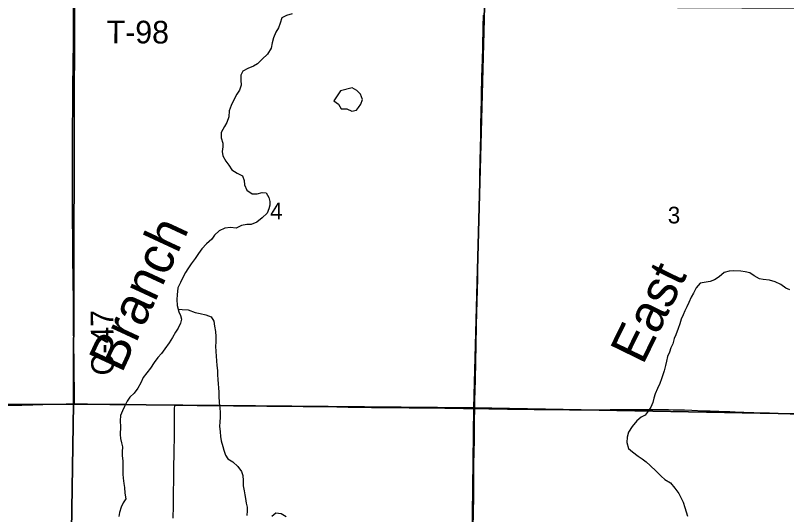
# Model space of a CAD drawing. Extents: x 0 to 34, y 0 to 22.
# Drawn here: x 3.385 to 4.352, y 16.769 to 17.395 of the extents above; entities that cross this region are included whole.
import ezdxf

# ---------------------------------------------------------------- set-up
doc = ezdxf.new("R2010")
doc.units = 0
for name, color, linetype in [('GM_X_County_Road', 7, 'Continuous'), ('GM_X_County_Road_Text', 7, 'Continuous'), ('GM_X_Minor_Lake', 7, 'Continuous'), ('GM_X_Minor_River', 7, 'Continuous'), ('GM_X_Minor_River_Text', 7, 'Continuous'), ('GM_X_Section', 7, 'Continuous'), ('GM_X_Section_Text', 7, 'Continuous'), ('GM_X_Township_Road', 7, 'Continuous'), ('GM_X_Township_Road_Text', 7, 'Continuous')]:
    doc.layers.add(name, color=color, linetype=linetype)

msp = doc.modelspace()

# ---------------------------------------------------------------- linework, layer by layer
at = {"layer": 'GM_X_County_Road'}
for points in [[(3.45945, 16.90815), (3.45949, 16.91151), (3.45951, 16.91491), (3.45933, 16.92889), (3.45926, 16.94257), (3.45913, 16.9522), (3.45894, 16.96494), (3.45873, 16.97769), (3.45843, 17.00846), (3.45828, 17.02711), (3.45821, 17.03643), (3.45806, 17.04483), (3.45798, 17.05509), (3.45793, 17.06285), (3.45785, 17.06782), (3.45775, 17.07248), (3.45755, 17.08304), (3.45746, 17.09236), (3.45733, 17.10572), (3.45725, 17.11412), (3.45711, 17.14023), (3.457, 17.15049), (3.45693, 17.16417), (3.45696, 17.18282), (3.45695, 17.20241), (3.45702, 17.21546), (3.457, 17.22852), (3.45711, 17.24096), (3.45718, 17.25277), (3.4572, 17.28199), (3.45746, 17.31121), (3.45766, 17.32893), (3.45804, 17.36748), (3.45838, 17.40478)], [(3.37291, 16.90601), (3.39342, 16.90665), (3.4074, 16.90706), (3.43287, 16.90789), (3.44904, 16.90816), (3.45931, 16.90815), (3.45945, 16.90815)], [(3.45945, 16.90815), (3.47577, 16.90794), (3.50218, 16.9076), (3.51554, 16.9075), (3.52394, 16.90749), (3.52798, 16.90742), (3.5373, 16.90715), (3.55345, 16.90698), (3.56184, 16.90685), (3.57178, 16.90673), (3.58503, 16.90663)], [(3.58312, 16.76464), (3.58337, 16.77956), (3.5836, 16.78919), (3.58376, 16.79757), (3.58387, 16.81186), (3.58411, 16.83051), (3.58433, 16.84419), (3.58454, 16.85506), (3.58464, 16.86097), (3.5848, 16.86903), (3.58475, 16.8771), (3.58475, 16.88021), (3.58484, 16.88767), (3.58498, 16.90135), (3.58503, 16.90663)], [(3.58503, 16.90663), (3.58763, 16.90662), (3.61312, 16.90613), (3.62088, 16.90602), (3.63579, 16.90592), (3.642, 16.90588), (3.64946, 16.90584), (3.65878, 16.90576), (3.66375, 16.9057), (3.67027, 16.90567), (3.67959, 16.9056), (3.70042, 16.90534), (3.72186, 16.90508), (3.73087, 16.905), (3.7461, 16.90483), (3.76226, 16.90462), (3.78805, 16.90439), (3.80235, 16.90414), (3.82069, 16.90385), (3.83188, 16.90366), (3.83808, 16.90357), (3.84944, 16.90354), (3.86309, 16.90335), (3.87893, 16.9032), (3.88888, 16.90318), (3.89976, 16.90311), (3.92338, 16.90277), (3.947, 16.90243), (3.95601, 16.90234), (3.96116, 16.9023)], [(3.96116, 16.9023), (3.97062, 16.90221), (3.9787, 16.90202), (3.99019, 16.90172), (4.0023, 16.90157), (4.01722, 16.90135), (4.02343, 16.90126), (4.02716, 16.90124), (4.03555, 16.90116), (4.04332, 16.90108), (4.05109, 16.90099), (4.05606, 16.90096), (4.06321, 16.90086), (4.0719, 16.90084), (4.07999, 16.90078), (4.08744, 16.90071), (4.09832, 16.90066), (4.10888, 16.90057), (4.11788, 16.90069), (4.13063, 16.90084), (4.14959, 16.90081), (4.15798, 16.90088), (4.16823, 16.90106), (4.1732, 16.90112), (4.1788, 16.90115), (4.18374, 16.9011), (4.18591, 16.90107), (4.18773, 16.90103), (4.18856, 16.901), (4.19227, 16.90099), (4.19755, 16.90095), (4.19783, 16.90093), (4.20279, 16.90088), (4.20401, 16.90087), (4.20961, 16.90078), (4.21737, 16.90061), (4.2239, 16.90038), (4.23321, 16.89997), (4.24781, 16.89952), (4.25589, 16.89924), (4.26675, 16.89882), (4.28072, 16.89834), (4.28724, 16.89806), (4.29842, 16.89777), (4.31084, 16.89733), (4.33041, 16.89662), (4.34781, 16.89599), (4.37296, 16.89492)]]:
    msp.add_lwpolyline(points, dxfattribs=at)
at = {"layer": 'GM_X_Minor_Lake'}
for points in [[(3.81528, 17.2799), (3.81818, 17.28383), (3.82025, 17.2899), (3.8178, 17.29634), (3.81345, 17.30127), (3.80739, 17.30449), (3.79302, 17.30088), (3.78451, 17.28799)], [(3.78451, 17.28799), (3.79038, 17.28382), (3.79359, 17.27832), (3.80078, 17.27795), (3.80702, 17.2753), (3.81288, 17.27662), (3.81528, 17.2799)]]:
    msp.add_lwpolyline(points, dxfattribs=at)
at = {"layer": 'GM_X_Minor_River'}
for points in [[(3.73212, 17.39736), (3.72531, 17.39527), (3.71926, 17.39224), (3.71737, 17.38579), (3.7151, 17.37991), (3.7117, 17.37422), (3.70886, 17.36721), (3.70735, 17.36095), (3.70584, 17.35413), (3.70149, 17.34673), (3.69487, 17.34028), (3.68901, 17.33459), (3.68371, 17.33156), (3.6769, 17.32852), (3.67029, 17.3253), (3.66802, 17.32018), (3.66802, 17.31392), (3.66839, 17.30786), (3.66631, 17.3016), (3.66291, 17.29648), (3.65932, 17.28927), (3.65591, 17.28226), (3.65345, 17.27581), (3.6527, 17.26804), (3.65024, 17.26083), (3.64759, 17.2559), (3.64343, 17.24832), (3.64324, 17.24168), (3.64532, 17.23524), (3.64532, 17.2305), (3.64438, 17.22443), (3.64532, 17.21932), (3.64911, 17.2123), (3.6527, 17.20756), (3.65686, 17.2015), (3.66348, 17.19733), (3.66991, 17.19411), (3.67218, 17.18805), (3.67237, 17.18293), (3.67539, 17.17591), (3.6822, 17.17156), (3.68844, 17.17156), (3.69449, 17.17327), (3.69979, 17.1727), (3.70319, 17.16682), (3.70433, 17.16209), (3.70414, 17.15735), (3.70319, 17.15261), (3.70111, 17.14711), (3.69468, 17.14161), (3.68788, 17.13611), (3.68088, 17.13326), (3.67539, 17.13326), (3.66877, 17.13193), (3.66215, 17.12852), (3.65478, 17.12928), (3.64797, 17.12851), (3.64059, 17.12529), (3.63492, 17.1196), (3.63171, 17.11486), (3.62509, 17.1086), (3.61922, 17.10272), (3.61487, 17.09685), (3.61052, 17.09021), (3.6058, 17.08376), (3.60145, 17.07751), (3.59861, 17.07277), (3.5952, 17.06651), (3.59218, 17.06044), (3.58896, 17.05362)], [(4.3558, 17.05128), (4.35088, 17.05321), (4.34447, 17.05762), (4.33766, 17.06109), (4.33066, 17.06323), (4.3227, 17.06424), (4.31796, 17.06503), (4.31116, 17.06849), (4.30568, 17.07252), (4.29981, 17.07351), (4.2945, 17.0745), (4.28559, 17.07495), (4.27989, 17.07461), (4.27362, 17.07295), (4.26751, 17.0673), (4.26141, 17.06356), (4.25589, 17.06151), (4.24848, 17.06043), (4.24354, 17.05933), (4.23876, 17.05348), (4.23529, 17.04706), (4.23241, 17.04177), (4.22932, 17.03534), (4.22682, 17.02967), (4.2245, 17.02476), (4.22219, 17.01965), (4.21987, 17.01436), (4.21793, 17.00849), (4.21618, 17.00281), (4.21327, 16.99487), (4.21115, 16.98995), (4.20921, 16.98352), (4.20689, 16.97841), (4.20495, 16.97293), (4.20282, 16.96744), (4.20145, 16.96157), (4.20008, 16.95608), (4.19833, 16.94965), (4.19677, 16.94435), (4.19503, 16.93943), (4.1929, 16.93375), (4.19, 16.92733), (4.1873, 16.92071), (4.18555, 16.91522), (4.18418, 16.90973), (4.18167, 16.90387), (4.17841, 16.89896), (4.17457, 16.89406), (4.16981, 16.89144), (4.16408, 16.88674)], [(3.58896, 17.05362), (3.58802, 17.0449), (3.58783, 17.03902), (3.5882, 17.03125), (3.59029, 17.02367), (3.59236, 17.01893), (3.5935, 17.01419), (3.59236, 17.00927), (3.58934, 17.0032), (3.58593, 16.99789), (3.58215, 16.99144), (3.57799, 16.98481), (3.5725, 16.97722), (3.56834, 16.97135), (3.56399, 16.96623), (3.55926, 16.95978), (3.55491, 16.95296), (3.55, 16.94708), (3.54565, 16.94101), (3.54243, 16.93438), (3.53865, 16.92774), (3.53411, 16.92168), (3.52881, 16.91637), (3.5256, 16.91125), (3.522, 16.90461), (3.51954, 16.8993), (3.51727, 16.89343), (3.51689, 16.8866), (3.51708, 16.87921), (3.5167, 16.86973), (3.51727, 16.86443), (3.51859, 16.85931), (3.51954, 16.85419), (3.51935, 16.84794), (3.51935, 16.84282), (3.51991, 16.83676), (3.5201, 16.83107), (3.5201, 16.825), (3.51991, 16.82008), (3.52067, 16.81496), (3.52142, 16.80832), (3.52199, 16.80302), (3.52275, 16.79601), (3.52369, 16.7888), (3.52048, 16.78387), (3.51802, 16.77857), (3.51575, 16.77193), (3.51499, 16.76662)], [(3.58947, 17.02665), (3.59445, 17.02633), (3.60182, 17.02595), (3.61052, 17.02254), (3.61714, 17.02122), (3.62414, 17.0197), (3.63057, 17.01724), (3.63416, 17.01174), (3.6351, 17.00549), (3.63605, 16.99904), (3.63643, 16.99241), (3.63643, 16.98559), (3.63605, 16.98028), (3.63642, 16.97383), (3.63718, 16.96777), (3.63756, 16.96208), (3.63793, 16.9564), (3.63869, 16.94995), (3.63888, 16.94465), (3.63926, 16.93858), (3.63963, 16.93308), (3.63982, 16.92816), (3.6402, 16.92285), (3.64039, 16.91773), (3.64096, 16.90996), (3.64171, 16.90295), (3.6419, 16.89745), (3.6419, 16.89157), (3.64152, 16.88494), (3.64133, 16.8802), (3.6419, 16.87319), (3.64246, 16.86712), (3.64322, 16.86182), (3.64549, 16.85462), (3.64662, 16.84988), (3.64851, 16.84381), (3.65154, 16.83907), (3.65797, 16.83529), (3.66402, 16.82941), (3.66856, 16.82335), (3.67045, 16.81823), (3.67101, 16.81179), (3.67101, 16.80515), (3.67196, 16.79909), (3.6729, 16.79416), (3.67385, 16.78923), (3.67479, 16.78336), (3.67574, 16.77862), (3.67574, 16.77388), (3.67536, 16.76801)], [(4.16408, 16.88674), (4.15815, 16.87958), (4.15355, 16.87278), (4.15198, 16.86616), (4.15174, 16.85952), (4.15377, 16.85211), (4.15886, 16.8479), (4.16584, 16.84253), (4.17075, 16.83908), (4.17603, 16.83544), (4.18093, 16.83085), (4.18828, 16.82359), (4.19449, 16.81728), (4.19939, 16.81326), (4.20619, 16.80885), (4.21202, 16.80235), (4.21671, 16.79549), (4.21933, 16.79073), (4.22213, 16.78464), (4.22455, 16.77798), (4.22622, 16.77285), (4.22751, 16.76734)], [(3.70675, 16.76707), (3.71167, 16.77124), (3.71847, 16.77049), (3.72471, 16.76689)]]:
    msp.add_lwpolyline(points, dxfattribs=at)
at = {"layer": 'GM_X_Section'}
for points in [[(2.95387, 17.41526), (2.95577, 17.41524), (3.45969, 17.40978), (3.45803, 16.9079), (2.95082, 16.90639)], [(3.97319, 17.40651), (3.95972, 16.90301), (3.45803, 16.9079), (3.45969, 17.40978), (3.95917, 17.40642)], [(3.97319, 17.40651), (4.45706, 17.40418), (4.4534, 16.89398), (3.95972, 16.90301)], [(2.95082, 16.90639), (3.45803, 16.9079), (3.45049, 16.40627), (2.94559, 16.40739)], [(3.45803, 16.9079), (3.95972, 16.90301), (3.95367, 16.40288), (3.45049, 16.40627)], [(3.95972, 16.90301), (4.4534, 16.89398), (4.44567, 16.39783), (3.95367, 16.40288)]]:
    msp.add_lwpolyline(points, close=True, dxfattribs=at)
at = {"layer": 'GM_X_Township_Road'}
for points in [[(3.96116, 16.9023), (3.96136, 16.9123), (3.96192, 16.93808), (3.96234, 16.96077), (3.96283, 16.9819), (3.96343, 17.00613), (3.96384, 17.0226), (3.96416, 17.03627), (3.96452, 17.05118), (3.96483, 17.06486), (3.9648, 17.07356), (3.96512, 17.08349), (3.96545, 17.09716), (3.96589, 17.11767), (3.96632, 17.13351), (3.96654, 17.1475), (3.96668, 17.15558), (3.96682, 17.16178), (3.96704, 17.16955), (3.96737, 17.18385), (3.96759, 17.19472), (3.96786, 17.21306), (3.96849, 17.24506), (3.96876, 17.255), (3.96911, 17.27738), (3.96933, 17.2867), (3.96946, 17.29571), (3.97012, 17.31777), (3.9707, 17.34014), (3.97109, 17.35506), (3.97163, 17.38147), (3.97194, 17.39545)], [(3.95808, 16.65268), (3.95826, 16.67146), (3.9586, 16.70689), (3.95883, 16.7305), (3.95915, 16.7507), (3.95963, 16.77339), (3.95977, 16.78924), (3.95988, 16.81069), (3.96012, 16.83306), (3.96065, 16.86258), (3.96075, 16.8803), (3.96084, 16.88868), (3.9611, 16.89955), (3.96116, 16.9023)]]:
    msp.add_lwpolyline(points, dxfattribs=at)

# ---------------------------------------------------------------- texts
at = {"layer": 'GM_X_County_Road_Text'}
msp.add_text('C-47', height=0.028409, rotation=90.67821, dxfattribs=at).set_placement((3.50901, 16.9438))
at = {"layer": 'GM_X_Minor_River_Text'}
for s, rotation, p in [('Branch', 65.0337, (3.51874, 16.94548)), ('East', 63.96994, (4.17177, 16.95583))]:
    msp.add_text(s, height=0.047365, rotation=rotation, dxfattribs=at).set_placement(p)
at = {"layer": 'GM_X_Section_Text'}
for s, p in [('4', (3.70466, 17.13957)), ('3', (4.203, 17.13441))]:
    msp.add_text(s, height=0.02093, rotation=0.00001, dxfattribs=at).set_placement(p)
at = {"layer": 'GM_X_Township_Road_Text'}
msp.add_text('T-98', height=0.028409, rotation=359.65113, dxfattribs=at).set_placement((3.49971, 17.36049))

doc.saveas('drawing.dxf')
